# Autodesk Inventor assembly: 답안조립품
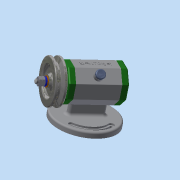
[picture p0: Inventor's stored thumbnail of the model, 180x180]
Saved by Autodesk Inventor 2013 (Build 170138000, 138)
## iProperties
Created: 2017-06
Part Number: 답안조립품
Document SubType Name: Assembly
Designer: Administrator
Author: Administrator
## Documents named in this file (14)
- C:\Users\Administrator\Desktop\470607V1013\답안조립품.iam
- C:\Users\Administrator\Desktop\470607V1013\V벨트풀리.ipt
- C:\Users\Administrator\Desktop\470607V1013\고무캡.ipt
- C:\Users\Administrator\Desktop\470607V1013\너트 M 8.ipt
- C:\Users\Administrator\Desktop\470607V1013\뒤커버.ipt
- C:\Users\Administrator\Desktop\470607V1013\베어링 15 x 32 x 9.ipt
- C:\Users\Administrator\Desktop\470607V1013\본체.ipt
- C:\Users\Administrator\Desktop\470607V1013\볼트 M4 x 12.ipt
- C:\Users\Administrator\Desktop\470607V1013\스프링와셔 8.ipt
- C:\Users\Administrator\Desktop\470607V1013\앞커버.ipt
- C:\Users\Administrator\Desktop\470607V1013\오일 실 15 25 7.ipt
- C:\Users\Administrator\Desktop\470607V1013\와셔 8x17.ipt
- C:\Users\Administrator\Desktop\470607V1013\축.ipt
- C:\Users\Administrator\Desktop\470607V1013\키 3 x 3 x 12.ipt
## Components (2 placed, 2 different names)
1. 고무캡:1
2. V벨트풀리:1 — 각도:2
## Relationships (1: Angle 1)
- 각도:2 [Angle]: V벨트풀리:1
